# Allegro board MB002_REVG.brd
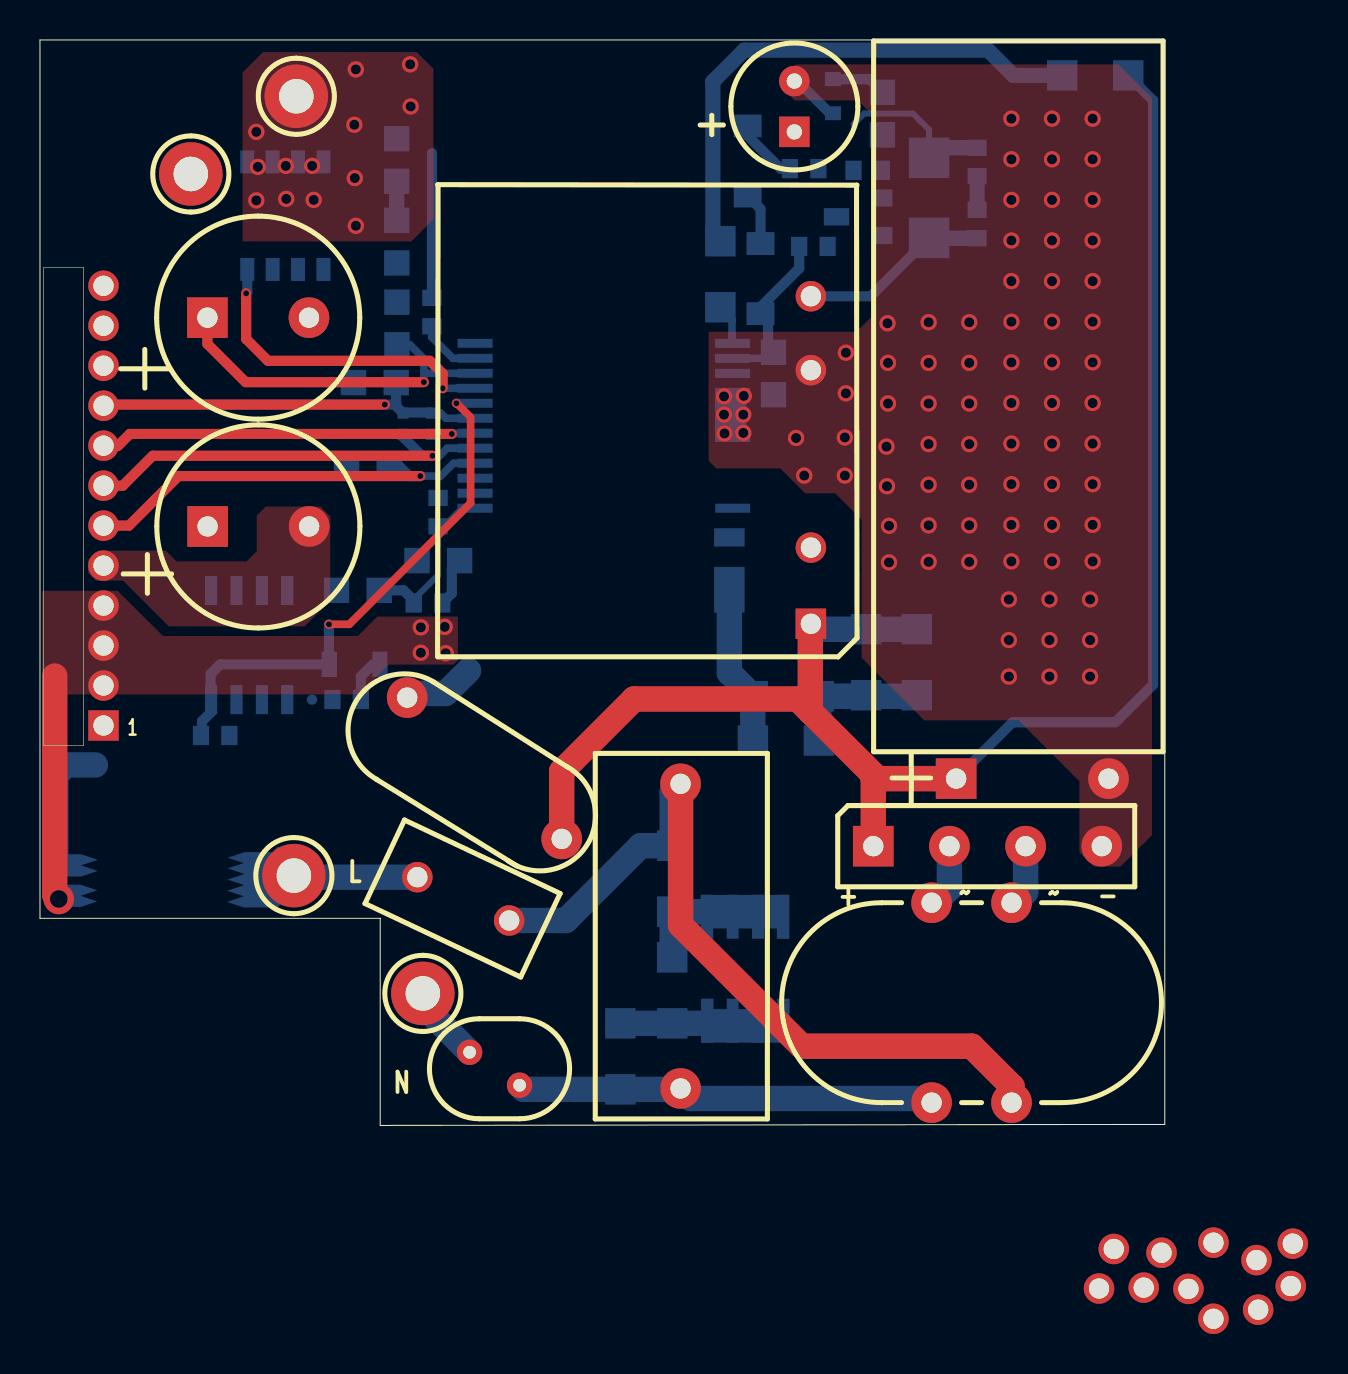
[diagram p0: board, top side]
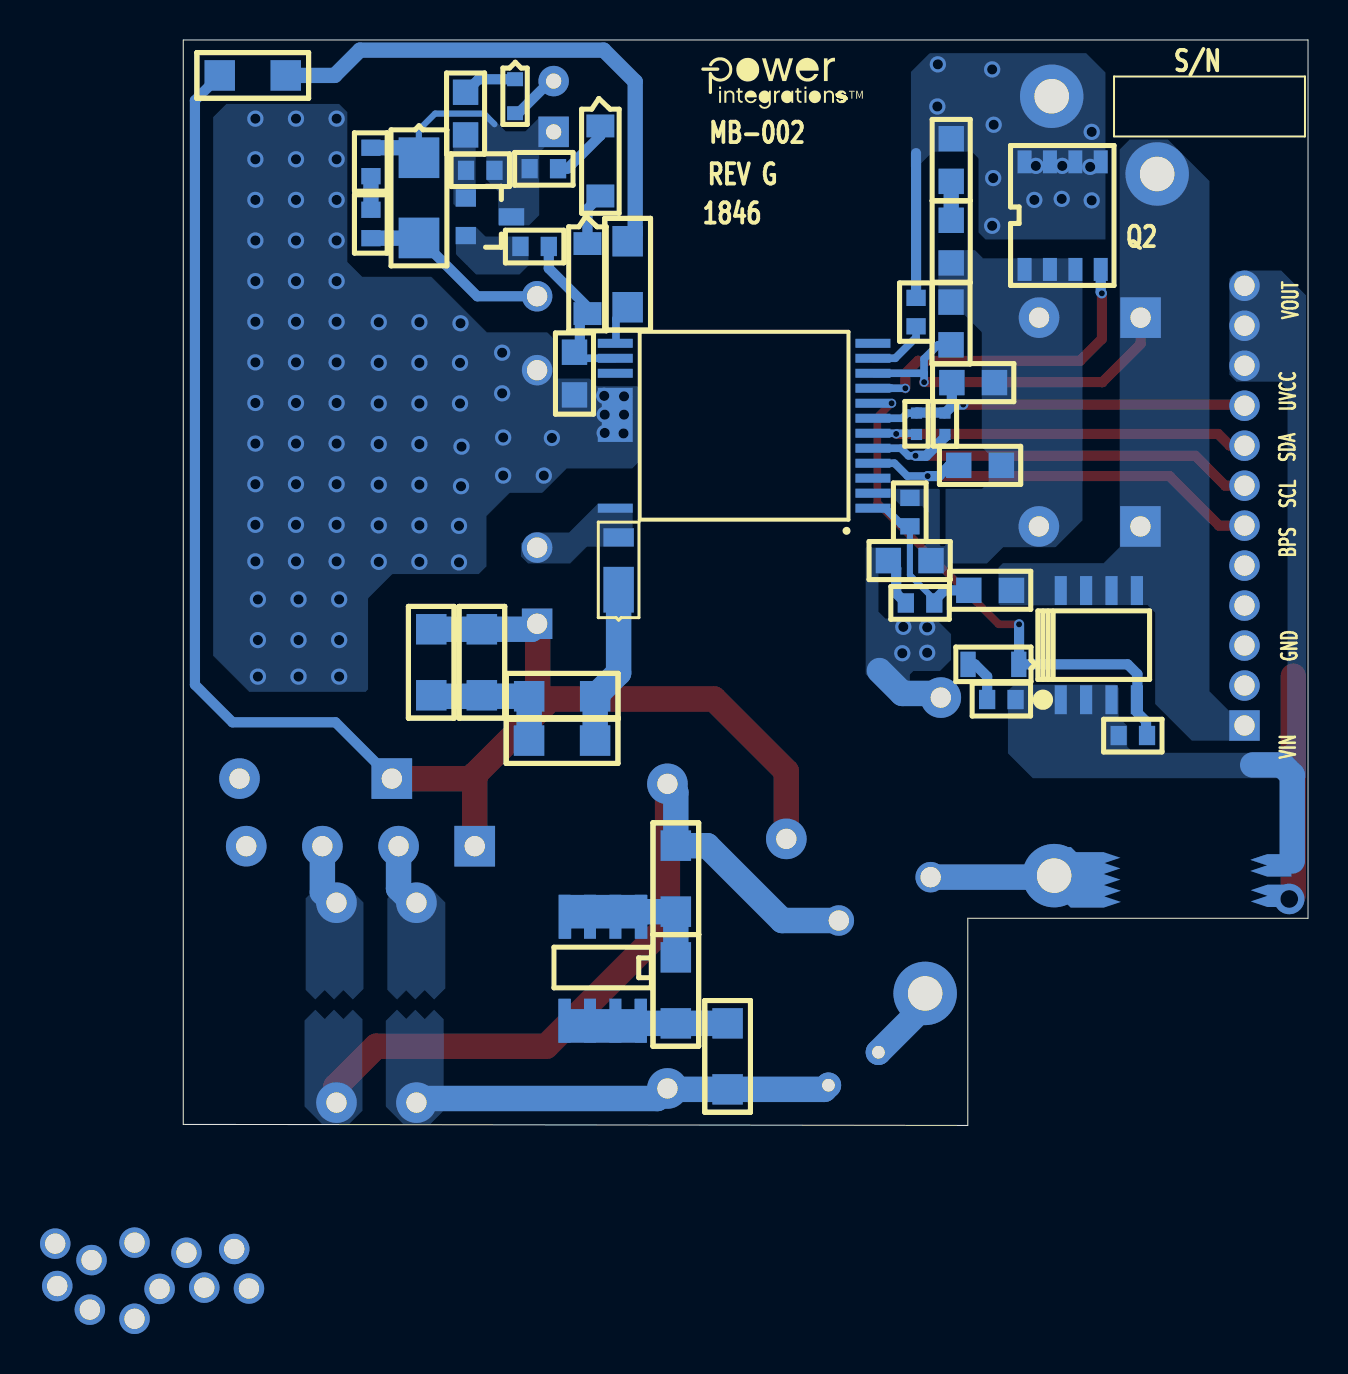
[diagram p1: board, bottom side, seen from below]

Outline 56.26 x 54.31 mm; copper layers: TOP, BOTTOM. Coordinates in mm from the lower left corner of the outline.
Outline path: 0,54.31 0,10.36 17.02,10.36 17.02,0 56.26,0.05 56.26,54.31 0,54.31

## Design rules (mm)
constraint set DEFAULT: min track width 0.508

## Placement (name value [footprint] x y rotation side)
BR1  KBP306G-BP  [PIDAXBRIDGEKBP306G]  41.68 13.97 0 top
C1  100 nF  [PINPXCAPRAD720X340600040]  32.04 17.09 270 top
C2  82 uF  [PIPOLCAPCLYD600LS300040]  45.83 17.35 0 bottom
C3  1 nF  [PINPYCAPRAD540X290LS400040]  26.1 14.34 151.6 top
C4  2.2 nF  [PISMC1206]  41.33 24.82 270 bottom
C5  56 pF  [PISMC0603]  46.87 45.81 270 bottom
C6  4.7 uF  [PISMC0805]  36.69 38.68 270 bottom
C7  22 uF  [PIPOLCAPCYLD250LS100030]  37.73 49.71 90 top
C8  1 nF  [PISMC0805]  17.85 45.28 270 bottom
C9  2.2 uF  [PISMC0805]  15.34 33.02 0 bottom
C10  2.2 uF  [PISMC0805]  17.86 41.19 270 bottom
C11  2.2 uF  [PISMC0805]  15.68 37.16 0 bottom
C12  470 uF  [PIPOLCAPCYLD400LS200040]  8.38 29.97 0 top
C13  470 uF  [PIPOLCAPCYLD400LS200040]  8.37 40.41 0 top
C14  4.7uF  [PISMC0603]  19.91 31.39 270 bottom
D1  DFLR1800-7  [PISMDDFLR120012]  34.48 26.78 270 bottom
D2  RS1J  [PISMDSMA]  44.47 48.41 270 bottom
D3  BAV21WS-7-F  [PISMSOD323]  14.47 23.07 0 bottom
F1  2 A  [PI_RST_MICROFUSE]  18.88 12.42 334.7 top
FL1  Hole_70mils  [PI_HOLE_70MIL]  7.55 47.63 180 top
FL2  Hole_70mils  [PI_HOLE_70MIL]  12.82 51.51 180 top
J1  PCB Terminal 18 AWG  [PI_HOLE_18AWG]  12.7 12.52 180 top
J2  PCB Terminal 18 AWG  [PI_HOLE_18AWG]  19.15 6.58 0 top
J3  CON15-DNP  [PI_UNSHROUD_2MM_15PRA]  3.18 20.01 90 top
L2  34 mH  [PI_CMCHOKE_19X10MM]  48.6 1.14 180 top
NOREF  -  []  -223.79 -144.72 0 top
NOREF#2  -  []  0 54.31 0 top
NOREF#3  -  []  56.21 0.05 90 top
NOREF#4  -  []  30.9 53.33 180 bottom
Q1  DSC2C01S0L  [PISMSOT23123_1]  42.13 44.52 270 bottom
Q2  SIR882ADP-T1-GE3  [PI_SM_POWERPAK_SO-8_SINGLE]  14.18 42.83 180 bottom
Q3  AO4354  [PISMSO8]  12.37 21.3 180 bottom
R1  1.91 M  [PISMR1206]  51.13 52.53 0 bottom
R2  1.80 M  [PISMR1206]  34.03 40.93 90 bottom
R3  232 k  [PISMR1206]  43.86 24.82 270 bottom
R4  40.2  [PISMR1206]  38.96 21.47 180 bottom
R5  22  [PISMR0603]  46.87 48.91 270 bottom
R6  22  [PISMR0603]  38.94 47.87 180 bottom
R7  6.49 k  [PISMR0603]  39.4 43.98 180 bottom
R8  267 k  [PISMR0603]  40.69 47.79 0 bottom
R9  10  [PISMR0805]  17.85 47.23 90 bottom
R10  47  [PISMR0603]  19.61 41.4 270 bottom
R11  0.009  [PISMR0805]  20.99 28.26 180 bottom
R13  100  [PISMR0603]  16.05 21.31 180 bottom
R14  4.70 k -DNP  [PISMR0402]  19.58 35.64 270 bottom
R15  4.70 k-DNP  [PISMR0402]  18.16 35.64 270 bottom
R16  2.2 M-DNP  [PISMR1206]  31.62 8.41 270 bottom
R17  2.2 M-DNP  [PISMR1206]  31.62 14 270 bottom
R18  2.2 M-DNP  [PISMR1206]  29.03 5.11 270 bottom
R20  226 k  [PISMR0805]  14.83 26.77 0 bottom
R21  10  [PISMR0603]  18.7 26.14 0 bottom
R22  40.2  [PISMR1206]  38.96 19.25 180 bottom
R23  30.1 k  [PISMR0805]  42.14 49.56 90 bottom
R24  470 k  [PISMR0603]  9.47 19.51 180 bottom
RT1  5  [PI_RAD_276DX197T_LS100D025]  23.99 2.83 180 top
T1  RM8  [PI_BOBBIN_RM8_12P]  38.56 25.1 180 top
U1  INN3368C  [PI_IC_INSOP_24D]  21.76 30.88 0 bottom
U3  CAP200DG-DNP  [PI_IC_SMD_SO8_CAPZERO]  33.38 10.44 0 bottom
VR1  DZ2S33000L  [PI_SM_D_SSMINI2P]  39.66 52.34 270 bottom
VR2  MMSZ5262BT1G  [PI_SM_SOD-123_12]  35.4 50.01 270 bottom
VR3  MMSZ5256B-7-F  [PI_SM_SOD-123_12]  36.04 44.12 270 bottom

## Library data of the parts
BR1 = DISCRETE BRIDGE_+~~-
C1 C4-C6 C9-C11 C14 = CAP NP
C2 = CAP POL: alternate symbols: (pipolcapd570ls3000401400lhoriz)
C3 = CAP NP: alternate symbols: (pinpycaprad540x290ls400040h,pinpycaprad500x220ls400040)
C7 = CAP POL: alternate symbols: (pipolcapcyld250ls100030h)
C8 = CAP NP: alternate symbols: (pismc0805_1)
C12 C13 = CAP POL
D1-D3 = DIODE
F1 = FUSE: alternate symbols: (pirstmicrofusehoz)
FL1 FL2 = FlyingLead
J1 J2 = TERM_1Pin
J3 = CON15
L2 = TORRID 4P_12_34: alternate symbols: (pi_CMChoke_19x10mmH)
Q1 = NPN_BEC
Q2 = FET_N_SGD_123_4_0
Q3 = FET_N_SGD_123_4_5678
R1-R9 R11 R13-R18 R20-R24 = R
R10 = R: alternate symbols: (pismr0603_1)
RT1 = THERMISTOR: alternate symbols: (pi_rad_276DX197Tls100d025H)
T1 = BRM8_12P/GENERIC: alternate symbols: (pi_bobbin_rm8_12p_inline_clp)
U1 = DEV_InnoPro
U3 = CAPZero
VR1-VR3 = DIODE_ZENER

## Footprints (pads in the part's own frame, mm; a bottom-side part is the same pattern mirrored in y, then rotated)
PI_BOBBIN_RM8_12P
  rect 1.524x1.524 hole 1.016: 1(0,0)
  round 1.524 hole 1.016: 2(0,-3.81) 3(-24.105,31.013) 4(0,-12.687) 5(0,-16.386) 6(-24.003,33.134) 7(-15.151,31.28) 8(-17.539,31.468) 9(-22.288,31.836) 10(-22.372,34.315) 11(-20.137,30.963) 12(-20.137,34.773)
PI_CMCHOKE_19X10MM
  round 2.032 hole 1.016: 1(0,0) 2(0,-10) 3(4,0) 4(4,-10)
PI_HOLE_18AWG
  round 3.175 hole 1.727: 1(0,0.025)
PI_HOLE_70MIL
  round 3.175 hole 1.727: 1(0,0.025)
PI_IC_INSOP_24D
  rect 1.75x0.45 smd: 1(0,0) 2(0,-0.75) 3(0,-1.5) 4(0,-2.25) 5(0,-3) 6(0,-3.75) 7(0,-4.5) 8(0,-5.25) 9(0,-6) 10(0,-6.75) 11(0,-7.5) 12(0,-8.25) 13(12.89,-8.25) 14(12.89,-7.5) 15(12.89,-6.75) 24(12.89,0)
  custom 0.438x0.438 smd: 16(12.89,-4.67)
PI_IC_SMD_SO8_CAPZERO
  rect 0.599x2.2 smd: 1(0,0) 2(1.27,0) 3(2.54,0) 4(3.81,0) 5(3.81,5.199) 6(2.54,5.199) 7(1.27,5.199) 8(0,5.199)
PI_RAD_276DX197T_LS100D025
  round 1.27 hole 0.635: 1(0,0.825) 2(2.5,-0.825)
PI_RST_MICROFUSE
  round 1.524 hole 1.016: 1(0,0) 2(5.08,0)
PI_SM_D_SSMINI2P
  rect 0.698x0.8 smd: 1(0,0) 2(1.7,0)
PI_SM_POWERPAK_SO-8_SINGLE
  rect 0.7x1.15 smd: 1(0,0) 2(1.27,0) 3(2.54,0) 4(3.81,0) 5(3.81,5.383) 6(2.54,5.383) 7(1.27,5.383) 8(0,5.383)
PI_SM_SOD-123_12
  rect 1.143x1.397 smd: 1(0,0) 2(3.505,0)
PI_UNSHROUD_2MM_15PRA
  rect 1.524x1.524 hole 1.016: 1(0,0)
  round 1.524 hole 1.016: 2(2,0) 3(4,0) 4(6,0) 5(8,0) 6(10,0) 7(12,0) 8(14,0) 9(16,0) 10(18,0) 11(20,0) 12(22,0) 13(-28.187,-54.268) 14(-28.168,-49.798) 15(-28.124,-52.033)
PIDAXBRIDGEKBP306G
  rect 2.032x2.032 hole 1.016: 1(0,0)
  round 2.032 hole 1.016: 2(3.81,0) 3(7.62,0) 4(11.43,0)
PINPXCAPRAD720X340600040
  round 2.032 hole 1.016: 1(0,0) 2(15.24,0)
PINPYCAPRAD540X290LS400040
  round 2.032 hole 1.016: 1(0,0) 2(10.16,-2.54)
PIPOLCAPCLYD600LS300040
  rect 2.032x2.032 hole 1.016: 1(0,0)
  round 2.032 hole 1.016: 2(7.62,0)
PIPOLCAPCYLD250LS100030
  rect 1.524x1.524 hole 0.762: 1(0,0)
  round 1.524 hole 0.762: 2(2.54,0)
PIPOLCAPCYLD400LS200040
  rect 2.032x2.032 hole 1.016: 1(0,0)
  round 2.032 hole 1.016: 2(5.08,0)
PISMC0603
  rect 0.813x0.965 smd: 1(0,0) 2(1.422,0)
PISMC0805
  rect 1.27x1.27 smd: 1(0,0) 2(2.134,0)
PISMC1206
  rect 1.524x1.524 smd: 1(0,0) 2(3.302,0)
PISMDDFLR120012
  rect 2.286x1.524 smd: 1(-0.025,0)
  rect 0.914x1.524 smd: 2(-2.642,0)
PISMDSMA
  rect 2.032x2.032 smd: 1(0,0) 2(4.013,0)
PISMR0402
  rect 0.559x0.559 smd: 1(0,0) 2(1.067,0)
PISMR0603
  rect 0.813x0.965 smd: 1(0,0) 2(1.422,0)
PISMR0805
  rect 1.27x1.27 smd: 1(0,0) 2(2.134,0)
PISMR1206
  rect 1.524x1.524 smd: 1(0,0) 2(3.302,0)
PISMSO8
  rect 0.61x1.448 smd: 1(0,0) 2(1.27,0) 3(2.54,0) 4(3.81,0) 5(3.81,5.461) 6(2.54,5.461) 7(1.27,5.461) 8(0,5.461)
PISMSOD323
  rect 0.762x1.27 smd: 1(0,0) 2(2.54,0)
PISMSOT23123_1
  rect 0.864x1.016 smd: 1(-1.88,0) 2(0,0)
  rect 0.864x1.27 smd: 3(-0.94,2.286)

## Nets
GND: C3.2 J3.2 J3.3 J3.4 R11.1 R21.2
GND_SIGNAL: C8.2 C9.1 C10.1 C11.1 C12.2 C13.2 C14.1 J3.5 Q2.1(S1) Q2.2 Q2.3 R11.2 U1.2
VBUS_IN: C10.2 C12.1 C13.1 FL1.1 J3.1 Q3.5 Q3.6 Q3.7 Q3.8 R20.1 U1.10(VOUT)
VBUS_OUT: J3.10 J3.11 J3.12 Q3.1 Q3.2 Q3.3(S3) R13.2 R24.1
BPS: C9.2 J3.6 U1.4
D1: FL2.1 Q2.5 Q2.6 Q2.7 Q2.8 R9.2 R10.1
IS: C14.2 R20.2 R21.1 U1.1
SCL: J3.7 R15.2 U1.5
SDA: J3.8 R14.2 U1.6
UVCC: C11.2 J3.9 R14.1 R15.1 U1.7
N11110124: C1.1 F1.2 L2.1 R17.1
N11110164: C1.2 L2.3 R18.2 RT1.1
N11110441: BR1.3(AC2) L2.2
N11110714: BR1.1 C2.1 C3.1 C4.1 R1.2 R3.1 T1.1
N11110720: BR1.4 C2.2 C6.2 C7.2 T1.4 U1.16 VR1.2
N11110824: BR1.2 L2.4
N11111408: R1.1 R2.2
N11111567: C4.2 R3.2 R4.1 R22.1
N11111589: D1.1 R4.2 R22.2
N11115084: F1.1 J1.1
N11116283: D1.2 T1.2 U1.24
N11116458: R2.1 U1.13
N11116606: Q2.4 U1.9
N11117013: C8.1 R9.1
N11227812: R10.2 U1.11
N12069038: R6.2 VR2.1
N12069042: Q1.1 R8.2 R23.1
N12069064: C7.1 D2.1 Q1.3 R5.1 R6.1 R8.1
N12069074: Q1.2(EMITTER) R7.1
N12069082: C6.1 R7.2 U1.14 VR3.2
N12069477: C5.2 D2.2 T1.5
N12069537: C5.1 R5.2
N12070281: D3.1 Q3.4 R24.2 U1.8
N12070310: D3.2 R13.1
N12112337: J2.1 RT1.2
N12112817: R16.1 R17.2 U3.2
N12112832: R16.2 R18.1 U3.7
N12122775: VR2.2 VR3.1
N12144048: R23.2 VR1.1

Pads without a net: J3 13 14 15; T1 3 6 7 8 9 10 11 12; U1 3 12 15; U3 1 3 4 5 6 8

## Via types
v1: diameter 1.524, hole 0.889, TOP to BOTTOM, 1 via
v2: diameter 0.457, hole 0.305, TOP to BOTTOM, 9 vias
v3: diameter 0.813, hole 0.508, TOP to BOTTOM, 95 vias

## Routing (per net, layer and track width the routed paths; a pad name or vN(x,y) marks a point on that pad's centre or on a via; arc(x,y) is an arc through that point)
GND: length 17.5
  TOP w1.27: 0.74,22.48 0.74,11.53
  BOTTOM w0.508: 20.68,28.07 20.87,28.26 R11.1 20.6,27.87 20.6,26.62 R21.2
  BOTTOM w1.27: 21.44,22.76 20.29,21.61 18.58,21.61 C3.2
  vias: v3(19.05,24.92) v3(19.05,23.65) v3(20.24,24.94) v3(20.29,23.62)
VBUS_IN: length 18.7
  TOP w0.508: C13.1 8.37,39.1 10.29,37.19 v2(19.2,37.19)
  BOTTOM w0.381: 19.21,37.63 19.2,37.63 v2(19.2,37.19) ; 19.21,37.63 19.21,38.35 18.5,39.05 C10.2 ; 19.21,37.63 U1.10
  BOTTOM w0.508: 2.82,19.99 2.9,19.99 2.92,20.01 J3.1
VBUS_OUT: length 6.5
  BOTTOM w0.508: 13.61,21.31 13.6,21.3
  BOTTOM w1.27: 2.77,18.03 1.3,18.03 0.79,17.53 0.79,13.23
BPS: length 21.7
  TOP w0.508: J3.6 4.45,30.01 6.93,32.49 v2(19.02,32.49)
  BOTTOM w0.381: U1.4 20.68,33.13 20.04,32.49 v2(19.02,32.49)
  BOTTOM w0.508: v2(19.02,32.49) 18.47,32.49 17.93,33.02 C9.2
D1: length 7.2
  BOTTOM w0.508: 19.61,48.64 R10.1
  vias: v3(10.82,49.71) v3(10.82,46.28) v3(10.9,47.96) v3(12.29,48.01) v3(12.32,46.35) v3(13.61,48.01) v3(13.69,46.3) v3(15.72,50.06) v3(15.75,47.4) v3(15.8,52.83) v3(15.8,45.01) v3(18.52,53.09) v3(18.54,50.98)
IS: length 8.6
  BOTTOM w0.305: 18.7,26.26 18.7,26.32 19.91,27.53 C14.2 ; 20.4,30.05 20.32,30.05
  BOTTOM w0.381: U1.1 21.15,30.88 20.32,30.05 19.99,30.05 C14.2
  BOTTOM w0.508: R21.1 18.7,26.26 18.19,26.77 R20.2
Net_8: length 0.3
  TOP w1.27: 0.76,11.51 v1(0.94,11.33)
SCL: length 21.4
  TOP w0.508: J3.7 4.14,32.01 5.64,33.5 v2(19.63,33.5)
  BOTTOM w0.381: v2(19.63,33.5) 19.99,33.5 20.37,33.88 U1.5
  BOTTOM w0.508: v2(19.63,33.5) 19.1,33.5 18.16,34.44 R15.2
SDA: length 19.9
  TOP w0.508: J3.8 3.91,34.01 4.5,34.59 v2(20.6,34.59)
  BOTTOM w0.381: R14.2 19.58,34.59 19.62,34.63 20.56,34.63 ; 20.56,34.63 U1.6 ; 20.56,34.63 v2(20.6,34.59)
UVCC: length 20
  TOP w0.508: J3.9 3.23,36.06 v2(17.25,36.06)
  BOTTOM w0.381: U1.7 20.3,35.38 20.04,35.64 19.61,35.64
  BOTTOM w0.508: 19.61,35.64 R14.1 19.56,35.66 18.19,35.66 R15.1 17.73,36.06 ; 17.73,36.06 v2(17.25,36.06) ; 17.73,36.06 17.82,36.15 C11.2
N11110124: length 40.8
  TOP w1.27: C1.1 32.04,10.02 38.1,3.96 46.61,3.96 48.62,1.95 48.62,1.24 48.6,1.22 L2.1
  BOTTOM w1.27: F1.2 26.3,10.25 30.05,14 R17.1 31.62,16.67 C1.1
N11110164: length 21.1
  BOTTOM w1.27: RT1.1 24.2,1.8 R18.2 32,1.8 C1.2 32.55,1.35 44.32,1.35 44.34,1.32 44.5,1.32 44.6,1.22 L2.3
N11110441: length 3.3
  BOTTOM w1.27: BR1.3 49.3,11.67 48.95,11.32 48.7,11.32 48.6,11.22 L2.2
N11110714: length 82.4
  TOP w1.27: C3.1 26.1,17.71 29.72,21.34 37.9,21.34 38.53,20.7 ; 38.53,20.7 38.53,25.07 T1.1 ; 38.53,20.7 41.68,17.55 41.68,17.35 ; BR1.1 41.68,17.35 ; 41.68,17.35 C2.1
  BOTTOM w0.508: R1.2 54.44,52.52 55.68,51.28 55.68,22.05 53.8,20.17 48.65,20.17 C2.1
  BOTTOM w1.27: T1.1 38.84,24.82 C4.1 R3.1
N11110720: length 2.6
  BOTTOM w0.508: C7.2 37.9,52.25 39.5,50.64 VR1.2
  vias: v3(34.21,36.47) v3(34.21,35.56) v3(34.24,34.62) v3(35.2,36.5) v3(35.18,35.56) v3(35.18,34.65) v3(37.82,34.39) v3(38.23,32.51) v3(40.31,38.66) v3(40.31,36.63) v3(40.26,34.42) v3(40.26,32.51) v3(42.34,33.96) v3(42.39,40.13) v3(42.42,38.15) v3(42.42,36.12) v3(42.37,31.98) v3(42.47,30) v3(42.47,28.17) v3(44.45,40.18) v3(44.45,38.15) v3(44.45,36.12) v3(44.45,34.09) v3(44.45,32.05) v3(44.45,30.02) v3(44.45,28.19) v3(46.48,40.18) v3(46.48,38.15) v3(46.48,36.12) v3(46.48,34.09) v3(46.48,32.05) v3(46.48,30.02) v3(46.48,28.19) v3(48.46,26.31) v3(48.46,24.28) v3(48.46,22.45) v3(48.59,50.37) v3(48.59,48.34) v3(48.59,46.3) v3(48.59,44.27) v3(48.59,42.24) v3(48.59,40.21) v3(48.59,38.18) v3(48.59,36.14) v3(48.59,34.11) v3(48.59,32.08) v3(48.59,30.05) v3(48.59,28.22) v3(50.5,26.31) v3(50.5,24.28) v3(50.5,22.45) v3(50.62,50.37) v3(50.62,48.34) v3(50.62,46.3) v3(50.62,44.27) v3(50.62,42.24) v3(50.62,40.21) v3(50.62,38.18) v3(50.62,36.14) v3(50.62,34.11) v3(50.62,32.08) v3(50.62,30.05) v3(50.62,28.22) v3(52.53,26.31) v3(52.53,24.28) v3(52.53,22.45) v3(52.65,50.37) v3(52.65,48.34) v3(52.65,46.3) v3(52.65,44.27) v3(52.65,42.24) v3(52.65,40.21) v3(52.65,38.18) v3(52.65,36.14) v3(52.65,34.11) v3(52.65,32.08) v3(52.65,30.05) v3(52.65,28.22)
N11110824: length 3.3
  BOTTOM w1.27: BR1.2 45.49,11.86 44.95,11.32 44.7,11.32 44.6,11.22 L2.4
N11111408: length 26.8
  BOTTOM w0.762: R2.2 33.66,44.61 33.66,52.22 35.23,53.8 47.42,53.8 48.69,52.53 R1.1
N11111567: length 7.2
  BOTTOM w1.27: R3.2 43.8,21.47 41.38,21.47 C4.2 41.28,21.47 R4.1 38.96,19.26 R22.1
N11111589: length 8
  BOTTOM w1.27: D1.1 34.48,22.64 R4.2 35.66,19.26 R22.2
N11115084: length 6.2
  BOTTOM w1.27: J1.1 12.78,12.42 F1.1
N11116458: length 2.1
  BOTTOM w0.381: U1.13 34.62,39.17 34.62,40.35 R2.1
N11116606: length 16.4
  TOP w0.508: v2(20.14,36.88) 20.14,37.62 19.51,38.25 11.4,38.25 10.31,39.34 v2(10.31,41.63)
  BOTTOM w0.381: v2(20.14,36.88) 20.85,36.88 U1.9
  BOTTOM w0.508: Q2.4 10.37,41.69 v2(10.31,41.63)
N11117013: length 1.9
  BOTTOM w0.762: R9.1 C8.1
N11227812: length 3.1
  BOTTOM w0.381: U1.11 20.65,38.38 19.61,39.42 R10.2
N12069038: length 3.3
  BOTTOM w0.508: VR2.1 35.4,49.51 37.05,47.87 R6.2
N12069064: length 8.3
  BOTTOM w0.305: 44.48,48.42 44.48,49.81 43.66,50.62 41.22,50.62 40.69,50.09
  BOTTOM w0.762: D2.1 44.97,48.91 R5.1
N12069082: length 8.5
  BOTTOM w0.381: U1.14 36.26,38.38 36.57,38.68 C6.1
  BOTTOM w0.508: R7.2 37.98,42.88 36.04,40.94 VR3.2 36.42,40.23 36.42,38.95 C6.1
N12069477: length 9.5
  BOTTOM w0.508: T1.5 41.55,41.48 44.47,44.4 D2.2
  BOTTOM w0.762: D2.2 44.48,44.39 C5.2
N12069537: length 1.7
  BOTTOM w0.762: R5.2 C5.1
N12070281: length 27.3
  TOP w0.381: v2(20.83,36.13) 20.84,36.13 21.54,35.43 21.54,31.14 15.47,25.07 v2(14.45,25.07)
  BOTTOM w0.381: U1.8 v2(20.83,36.13)
  BOTTOM w0.508: R24.2 8.1,19.56 8.1,20.22 8.56,20.68 Q3.4 8.53,21.32 8.53,22.58 9.02,23.07 D3.1 14.45,23.08 v2(14.45,25.07)
N12070310: length 2.4
  BOTTOM w0.508: R13.1 16.05,22.46 16.66,23.07 D3.2
N12112337: length 3.9
  BOTTOM w1.27: RT1.2 19.15,6 J2.1
N12112817: length 5.4
  BOTTOM w1.27: R16.1 R17.2 34.39,10.69 U3.2
N12112832: length 5.7
  BOTTOM w1.27: R18.1 R16.2 34.51,5.11 U3.7
N12122775: length 2.6
  BOTTOM w0.508: VR3.1 36.04,45.86 VR2.2
N12144048: length 2.7
  BOTTOM w0.508: R23.2 41.49,52.34 VR1.1

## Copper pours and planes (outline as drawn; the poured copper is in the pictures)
GND on BOTTOM (solid shape): 2.86,11.77 2.02,11.49 2.86,11.21 2.02,10.93 0.8,10.93 0.8,12.05 2.02,12.05
GND on TOP: 15.9,24.49 16.88,25.46 20.89,25.46 20.9,25.45 20.9,23.27 20.69,23.05 17.44,23.05 15.95,21.56 0.13,21.56 0.1,21.59 0.1,26.75 3.89,26.75 6.15,24.49
GND on BOTTOM: 22.12,22.58 21.59,22.05 19.91,22.05 19.91,22.56 19.74,22.73 18.41,22.73 17.86,23.29 17.86,24.59 18.63,25.36 21.15,25.36 21.49,25.7 21.49,27.58 21.45,27.62 20.36,27.62 20.35,27.64 20.35,28.88 20.37,28.91 22.12,28.91
GND_SIGNAL on TOP: 6.3,28.75 6.83,28.22 10.34,28.22 10.85,28.73 10.85,30.51 11.3,30.96 14.02,30.96 14.53,30.45 14.53,29.46 14.52,29.45 14.52,26.25 13.23,24.97 6.45,24.97 4.17,27.25 2.79,27.25 2.4,27.65 2.4,28.28 2.87,28.75
GND_SIGNAL on BOTTOM: 11.28,43.38 16.28,43.38 16.28,43.41 16.66,43.79 18.47,43.79 18.49,43.76 18.49,40.56 17.2,40.56 16.32,39.69 16.32,33.95 15.98,33.6 15.98,32.18 16.31,31.85 18.14,31.85 18.14,29.03 18.19,28.98 18.36,28.98 18.41,29.03 18.41,31.8 18.47,31.85 22.61,31.85 22.63,31.83 22.63,31.42 20.78,31.42 20.35,30.99 19.28,30.99 19.28,30.96 18.95,30.63 18.95,29.24 19.25,28.93 19.51,28.93 19.51,27.74 19.41,27.64 18.24,27.64 18.03,27.84 18.03,27.91 17.83,28.12 16.05,28.12 15.24,28.93 12.62,28.93 11.28,30.28
VBUS_IN on BOTTOM: 2.39,19.25 5.82,19.25 7.65,21.08 7.65,25.65 8.03,26.04 12.67,26.04 12.69,26.02 15.41,26.02 15.48,26.1 15.48,27.91 15.27,28.13 10.22,28.13 9.42,28.93 9.42,48.82 8.92,49.33 7.01,49.33 4.93,47.24 4.93,21.72 3.96,20.75 2.41,20.75 2.41,19.28
VBUS_OUT on BOTTOM (solid shape): 2.89,13.29 2.05,13.01 2.89,12.73 2.05,12.45 0.83,12.45 0.83,13.57 2.05,13.57
VBUS_OUT on BOTTOM: 0.13,17.37 0.1,17.4 0.1,41.53 1.35,42.77 3.23,42.77 3.25,42.75 3.56,42.75 3.94,42.37 3.94,37.57 3.58,37.21 1.45,37.21 1.03,36.79 1.03,19.09 1.47,18.64 8.74,18.64 9.04,18.95 9.04,19.99 9.47,20.42 9.47,21.89 9.63,22.05 14.71,22.05 15.01,21.74 15.01,18.62 13.77,17.37
D1 on TOP: 11.15,53.7 18.85,53.7 19.68,52.86 19.68,45.34 18.57,44.22 10.13,44.22 10.13,52.68
D1 on BOTTOM: 10.13,44.32 16.13,44.32 16.48,44.68 16.48,48.39 16.81,48.72 18.77,48.72 19.53,47.96 19.86,47.96 19.86,52.7 18.92,53.64 11.1,53.64 10.13,52.68
Net_48 on BOTTOM (solid shape): 33.68,5.82 36.88,5.82 36.88,6.32 37.49,6.32 37.49,4.14 33.07,4.14 33.07,6.32 33.68,6.32
Net_52 on BOTTOM (solid shape): 37.47,9.35 36.86,9.35 36.86,9.86 33.66,9.86 33.66,9.35 33.05,9.35 33.05,11.53 37.47,11.53
N11110124 on BOTTOM: 47.29,0.74 47.29,5.31 47.78,5.79 48.25,5.32 48.72,5.79 49.17,5.33 49.2,5.33 49.66,5.79 50.19,5.26 50.19,0.94 49.33,0.08 47.96,0.08
N11110164 on BOTTOM: 43.23,0.74 43.23,5.31 43.71,5.79 44.18,5.32 44.65,5.79 45.11,5.33 45.57,5.79 46.13,5.23 46.13,0.94 45.26,0.08 43.89,0.08
N11110441 on BOTTOM: 50.14,11.35 50.14,6.78 49.66,6.3 49.19,6.77 48.72,6.3 48.26,6.76 48.23,6.76 47.78,6.3 47.24,6.83 47.24,11.15 48.11,12.01 49.48,12.01
N11110720 on TOP: 37.29,52.55 37.82,53.09 53.95,53.09 55.62,51.41 55.62,14.53 54.04,12.94 52.72,12.94 51.99,13.67 51.99,17.22 48.95,20.27 44.22,20.27 41.1,23.39 41.1,30.3 39.78,31.62 38.28,31.62 37.03,32.87 33.83,32.87 33.44,33.26 33.44,39.7 38.25,39.7 38.27,39.69 38.28,39.7 40.84,39.7 41.78,40.64 41.78,41.77 41.79,41.78 41.79,50.41 40.92,51.28 37.74,51.28 37.29,51.74
N11110720 on BOTTOM: 48.05,43.2 48.05,50.7 48.46,51.1 54.1,51.1 54.76,50.44 54.76,23.5 52.96,21.69 47.14,21.69 47.02,21.82 47.02,26.37 45.8,27.58 41.48,27.58 41.1,27.97 41.1,30.48 39.93,31.65 38.3,31.65 37.08,32.87 33.81,32.87 33.44,33.24 33.44,36.98 35.56,36.98 35.94,37.36 37.64,37.36 37.8,37.52 37.8,39.42 38.05,39.67 41.07,39.67 43.85,42.46 47.31,42.46
N11110824 on BOTTOM: 46.05,11.35 46.05,6.78 45.57,6.3 45.11,6.76 44.65,6.3 44.2,6.76 44.17,6.76 43.71,6.3 43.15,6.86 43.15,11.15 44.02,12.01 45.39,12.01
N11115084 on BOTTOM (solid shape): 13.42,13.59 13.42,12.44 11.88,10.9 10.2,10.9 9.36,11.18 10.2,11.46 9.36,11.74 10.2,12.02 10.21,12.03 9.39,12.3 10.23,12.58 9.39,12.86 10.19,13.12 9.39,13.39 10.23,13.67 10.23,13.67 11.61,13.67 11.86,13.93 13.08,13.93
N11116283 on BOTTOM: 35.51,31.11 33.79,31.11 33.79,31.1 33.78,31.09 33.78,28.96 36.07,28.96 36.91,28.12 39.01,28.12 39.37,28.47 39.37,29.11 38.81,29.67 38.81,29.67 36.96,29.67
N12069042 on BOTTOM: 42.75,50.16 42.75,46.1 42.62,45.97 41.63,45.97 41.63,50.14 41.66,50.16
N12069064 on BOTTOM: 38.46,50.44 38.46,50.42 39.14,49.73 40.13,49.73 40.69,50.29 41.07,50.29 41.1,50.27 41.1,47.32 40.51,46.74 40.51,45.09 40.46,45.03 38.96,45.03 38.46,45.54 38.46,48.67 38.18,48.95 36.98,48.95 36.98,50.44
N12069074 on BOTTOM: 38.99,44.48 41.15,44.48 41.61,44.93 42.62,44.93 42.62,43.59 41.61,42.57 39.45,42.57 38.99,43.03

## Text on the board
Ref Des/Silkscreen Bottom: VOUT | GND | UVCC | SCL | BPS | VIN | SDA | S/N | MB-002 | REV G | 1846
Ref Des/Silkscreen Top: L | N
User.5: 11.  TRACE SPACE +/- 0.003" | 13. 6 LAYERS BOARD TOP,1, 2, 3, 4, BOTTOM. | 14. VIAS 3, 4, 7, 8, 9, 12, ARE COPPER FILLED.
User.6: SLOT | NOTES: UNLESS OTHERWISE SPECIFIED | 1.  THROUGH HOLES ARE PLATED THROUGH. | 2.  MATERIAL: BASE MATERIAL LAMINATED EPOXY | 3.  SOLDER PLATE WILL BE RoHS COMPLIANT. | 4.  SOLDER MASK LPI (LIQUID PHOTO IMAGEABLE) BOTH SIDES. COLOR GREEN. | 5.  SILKSCREEN TOP/BOTTOM SIDE. COLOR WHITE.(MIN.WIDTH 0.005" MAX.WIDTH 0.010") | 6.  FINISH TO BE SMOBC. | 7.  LEAD FREE HASL (HOT AIR SOLDER LEVEL) OR RoHS COMPLIANT. | 8.  BOARD DIMENTION +/- 0.005" | 9.  DRILL TOLERANCE+/-0.003" | 10.  TRACE WIDTH UNDER 0.010" +/- 0.002" | 11.  TRACE SPACE +/- 0.003" | 12.  MATERIAL FR4 COPPER 2 OZ TOTAL BOARD THICKNESS 0.062" | PLEASE DELETE THESE PINS | EXCEPTIONS WILL BE NOTED IN DRILL CHART "NOTE". | UL APPROVED MANUFACTURED SOURCE FOR FR4. | SOLDER MASK (REGISTRATION) -0/+0.003" | TRACE WIDTH OVER 0.011" +/- 0.005"
User.9: FIGURE | FINISHED_SIZE | 12.012 | 20.0 | 25.0 | 30.0 | 35.0 | 40.0 | 67.988 | DRILL CHART: TOP to BOTTOM | ALL UNITS ARE IN MILS | TOLERANCE_DRILL | +2.988/-2.988 | +0.0/-0.0 | PLATED | QTY | 9 | 95 | 2 | 1 | 12 | 22 | 13 | 4
